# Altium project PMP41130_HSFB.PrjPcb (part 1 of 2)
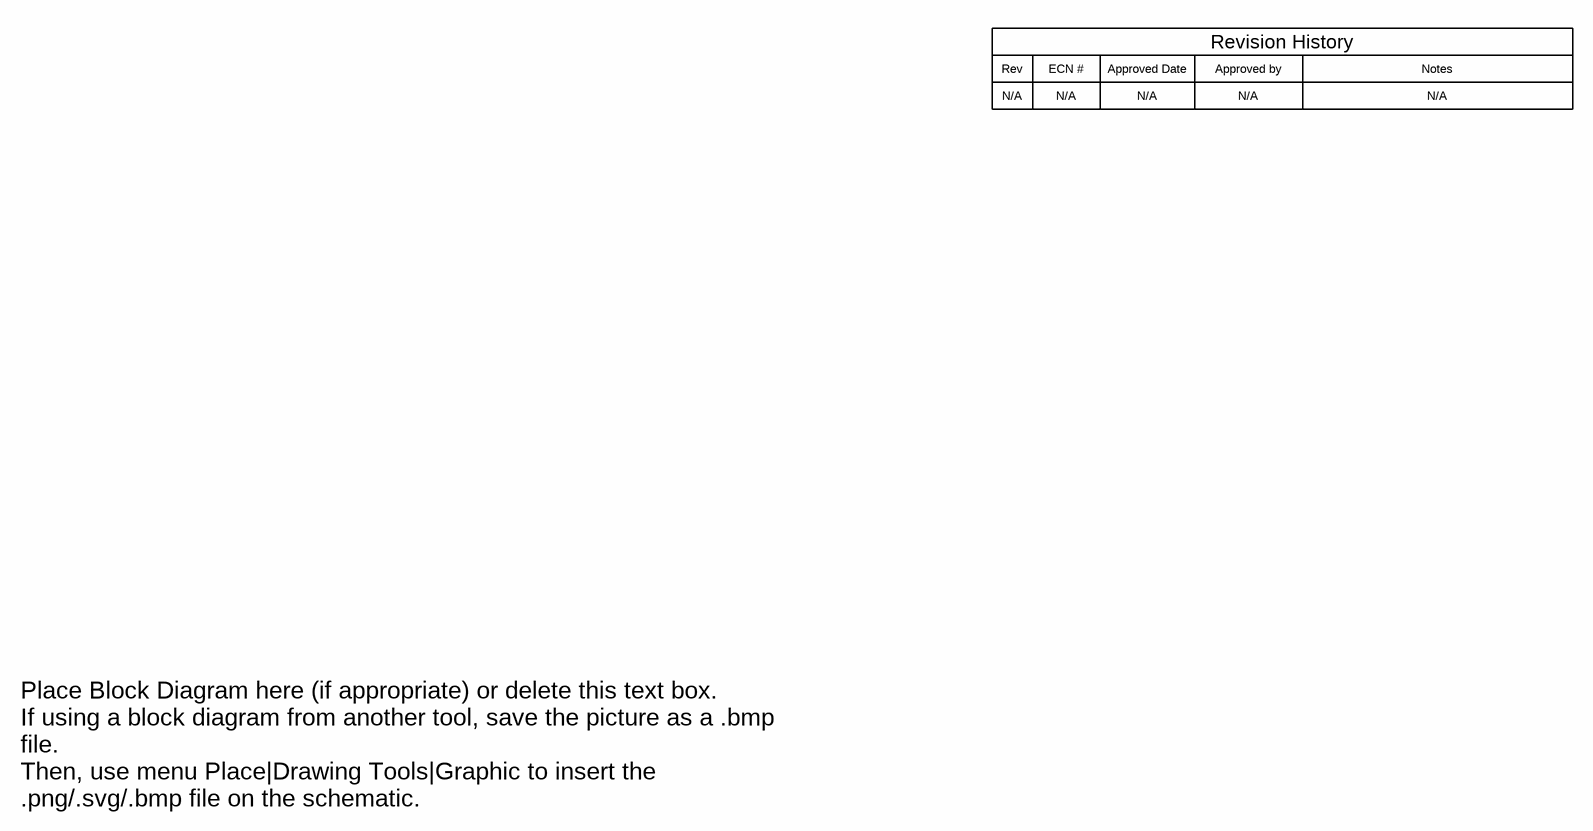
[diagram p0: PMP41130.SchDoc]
CopyrightYear: 2024; PCB_Layout: Xingqi (Eric) Chen; PCB_Rev: E1; PRJ_Customer: Public Release; PRJ_Engineer: Xingqi (Eric) Chen; PRJ_Number: PMP41130; PRJ_Title: PMP41130; SCH_Rev: E1; TechSupport: http://www.ti.com/support; TID: N/A
5 sheets, 369 parts. Net scope: global (net labels, ports and power ports of the same name join across sheets).
Board file: PMP41130_PCB.PcbDoc
Sheets:
  PMP41130.SchDoc
  PMP41130_PWR.SchDoc
  PMP41130_CTRL.SchDoc
  PMP41130_AUX.SchDoc
  PMP41130_Hardware.SchDoc

## Sheet PMP41130.SchDoc
size 431 x 279 mm; Date: Not shown in title block; ApprovedBy: Not shown in title block; CheckedBy: Not shown in title block; Author: Not shown in title block; CompanyName: Not shown in title block; Engineer: Not shown in title block; Organization: Not shown in title block; Address1: Not shown in title block; Address2: Not shown in title block; Address3: Not shown in title block; Address4: Not shown in title block; DocumentNumber: 1; Revision: Use project parameter SCH_Rev; SheetNumber: 1; SheetTotal: 5; PageSetup: Record=PageOptions¦CenterHorizontal=True¦CenterVertical=True¦PrintScale=1.00¦XCorrection=1.00¦YCorrection=1.00¦PrintKind=0¦BorderSize=5000000¦LeftOffset=0¦BottomOffset=0¦Orientation=2¦PaperLength=1000¦PaperWidth=1000¦Scale=100¦PaperSource=15¦PrintQuality=600¦MediaType=1¦DitherType=10¦PaperKind=Letter¦PrintScaleMode=1

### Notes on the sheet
- Rev
- N/A
- ECN #
- Approved Date
- Approved by
- Revision History
- Notes
- Place Block Diagram here (if appropriate) or delete this text box.
  If using a block diagram from another tool, save the picture as a .bmp file.
  Then, use menu Place|Drawing Tools|Graphic to insert the .png/.svg/.bmp file on the schematic.

## Sheet PMP41130_PWR.SchDoc
size A2; Date: Not shown in title block; ApprovedBy: Not shown in title block; CheckedBy: Not shown in title block; Author: Not shown in title block; CompanyName: Not shown in title block; Engineer: Not shown in title block; Organization: Not shown in title block; Address1: Not shown in title block; Address2: Not shown in title block; Address3: Not shown in title block; Address4: Not shown in title block; DocumentNumber: 1; Revision: Use project parameter SCH_Rev; SheetNumber: 2; SheetTotal: 5; PageSetup: Record=PageOptions¦CenterHorizontal=True¦CenterVertical=True¦PrintScale=0.69¦XCorrection=1.00¦YCorrection=1.00¦PrintKind=0¦BorderSize=5000000¦LeftOffset=0¦BottomOffset=0¦Orientation=2¦PaperLength=1000¦PaperWidth=1000¦Scale=100¦PaperSource=15¦PrintQuality=600¦MediaType=1¦DitherType=10¦PaperKind=Letter¦PrintScaleMode=1
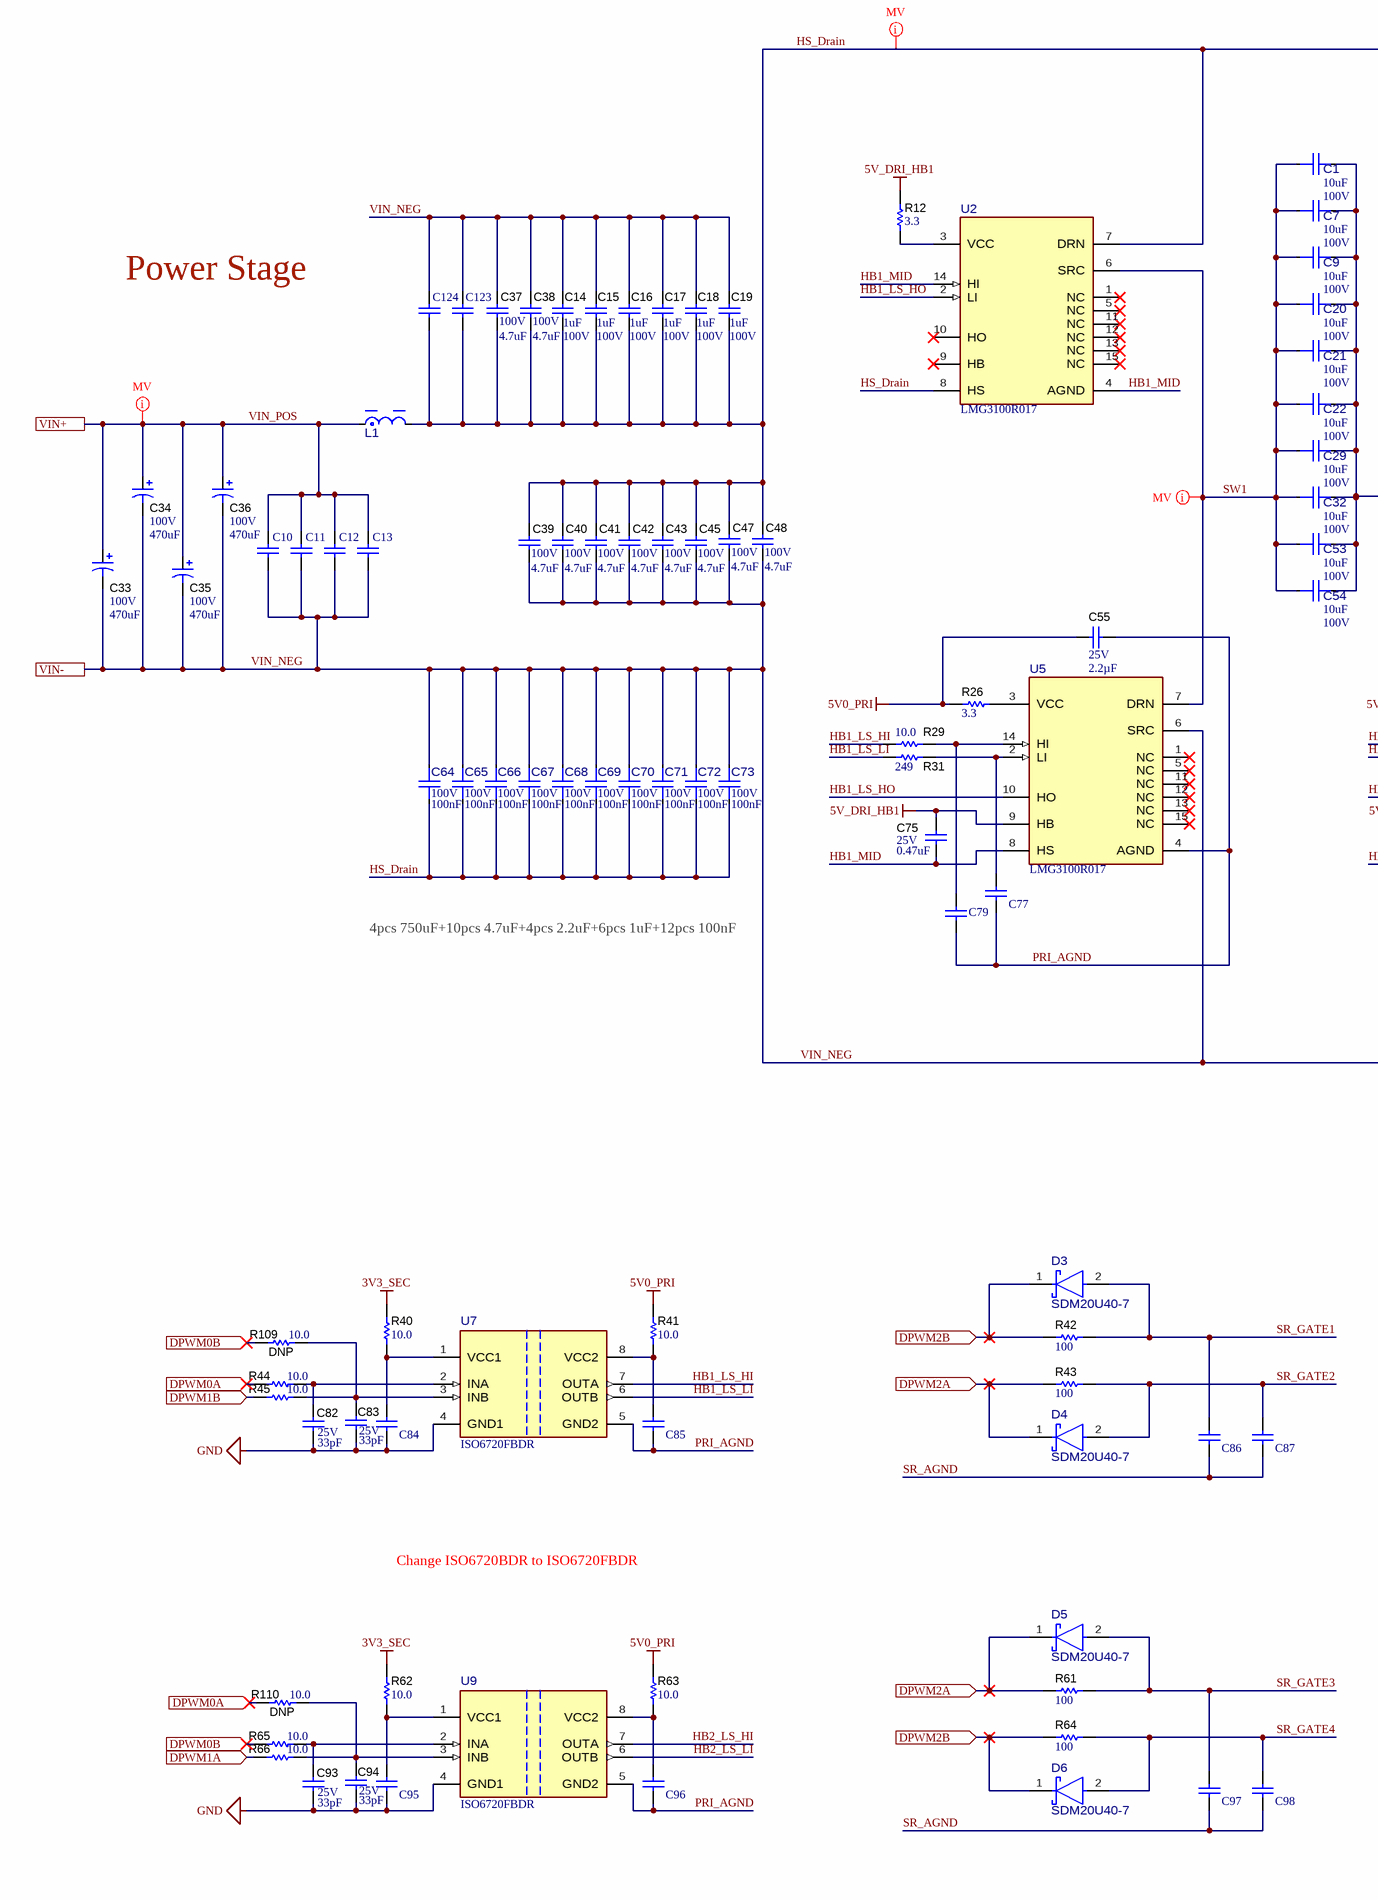
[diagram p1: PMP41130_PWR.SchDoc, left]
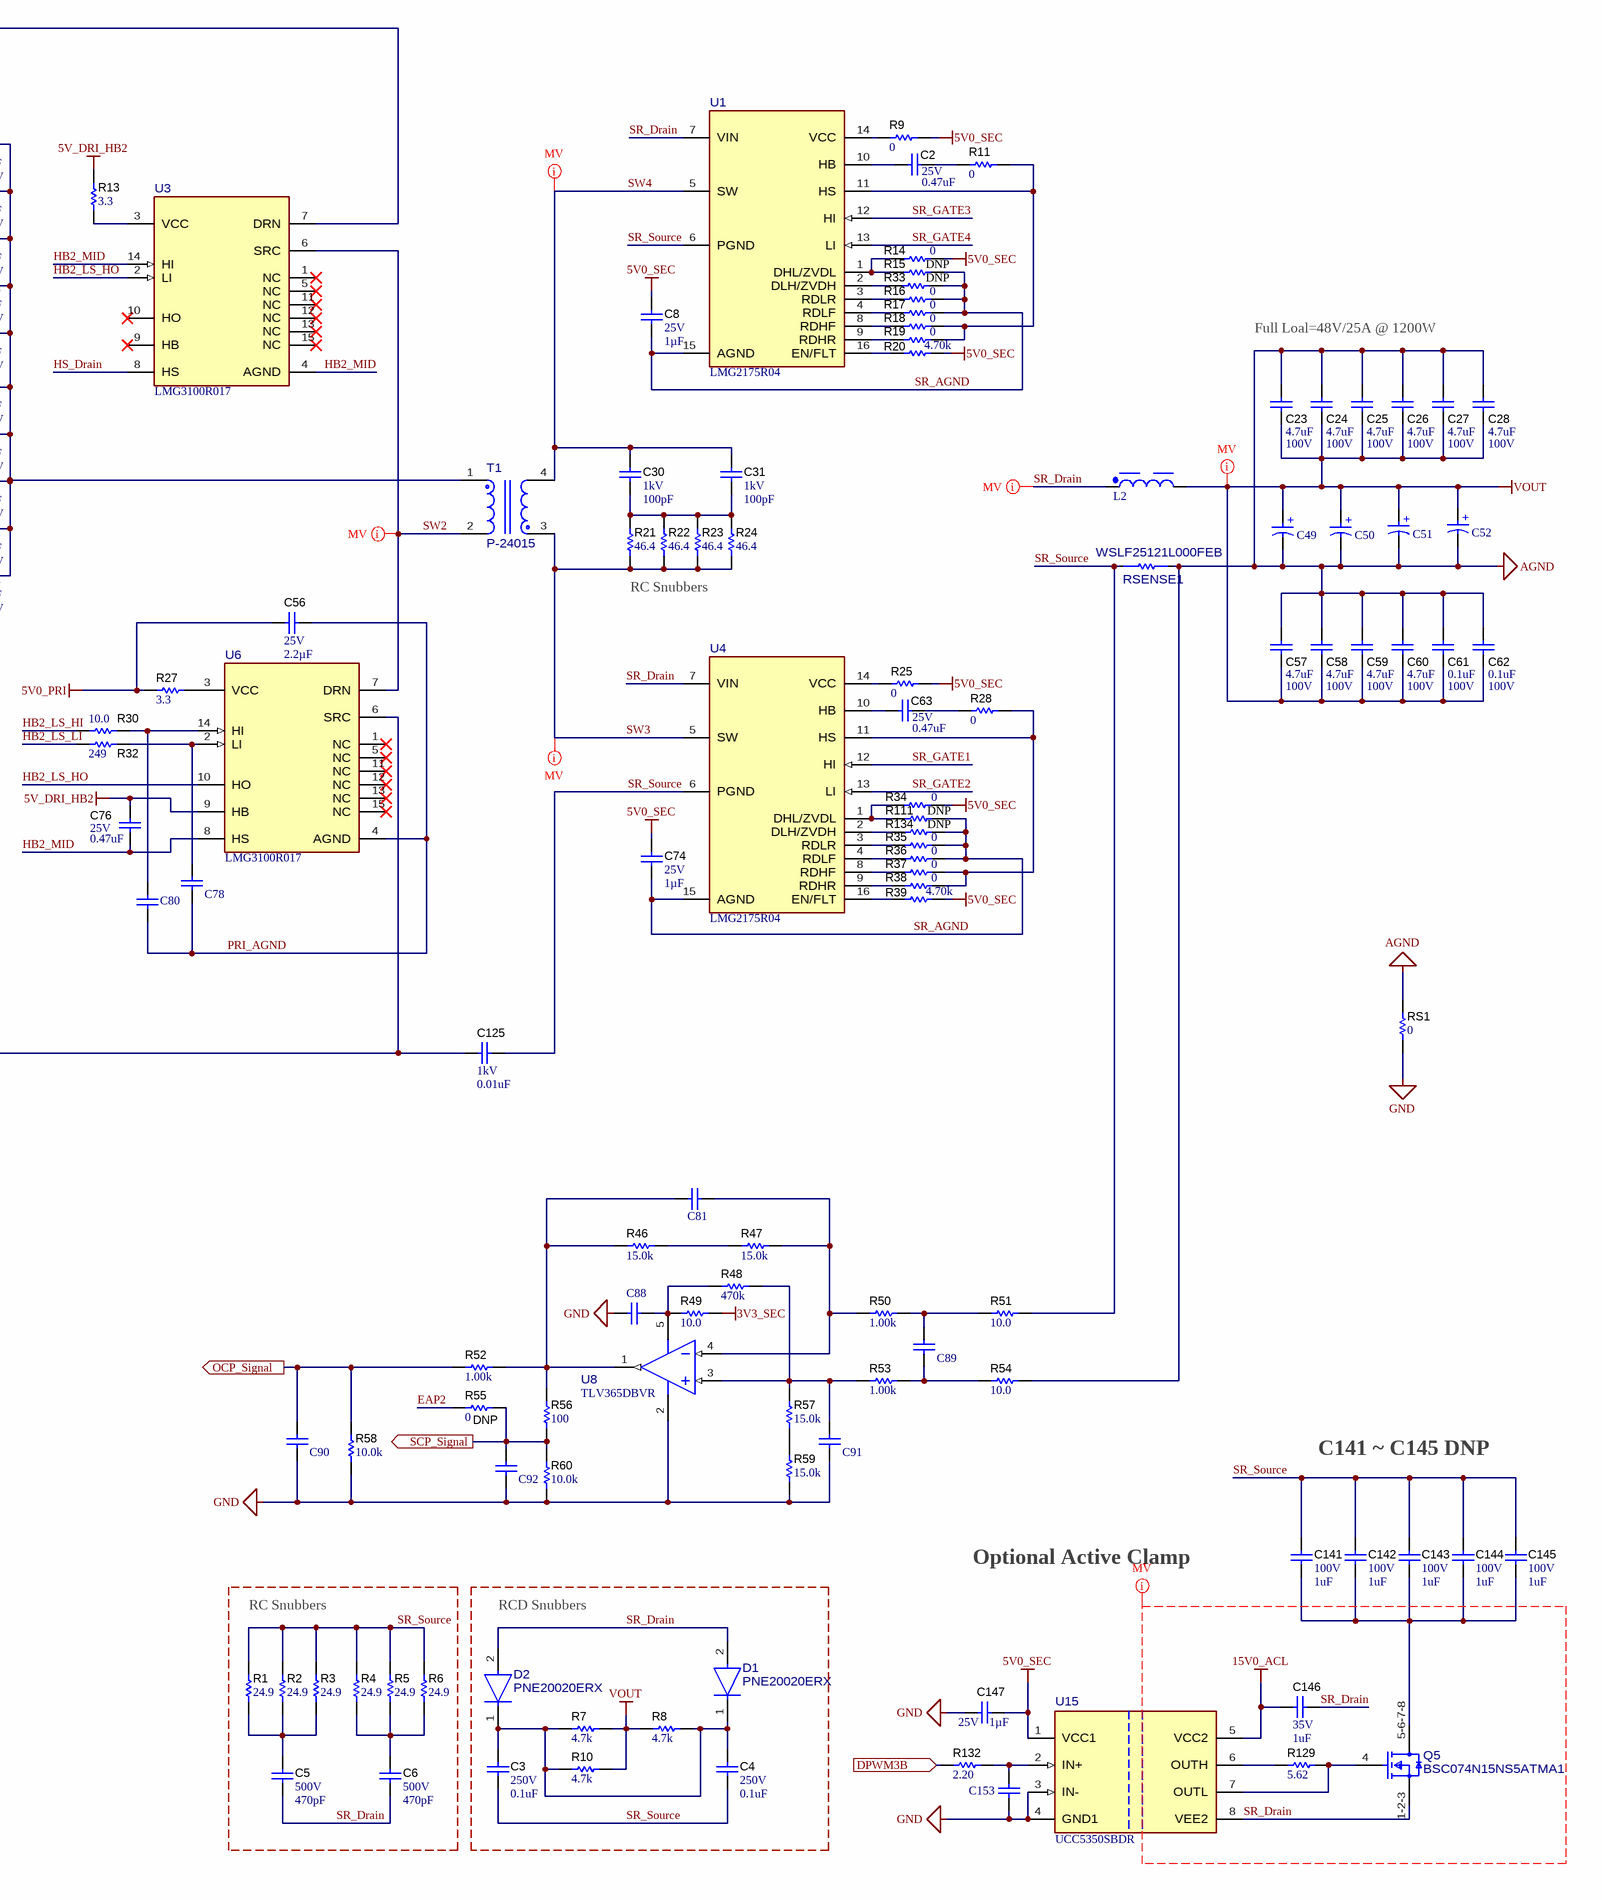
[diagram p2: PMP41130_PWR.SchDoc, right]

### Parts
C1  ValueDisplayed: 10uF  VDC_V: 100V  [FP-C3216X6S2A106K160AC_1206-MFG]  (hidden comment: C3216X6S2A106K160AC)
C2  VDC_V: 25V  ValueDisplayed: 0.47uF  [0402]  (hidden comment: GRM155R61E474KE01D)
C3  VDC_V: 250V  ValueDisplayed: 0.1uF  [0805_HV]  (hidden comment: C2012X7T2E104M125AE)
C4  VDC_V: 250V  ValueDisplayed: 0.1uF  [0805_HV]  (hidden comment: C2012X7T2E104M125AE)
C5  VDC_V: 500V  ValueDisplayed: 470pF  [1206]  (hidden comment: VJ1206Y471KXEAT5Z)
C6  VDC_V: 500V  ValueDisplayed: 470pF  [1206]  (hidden comment: VJ1206Y471KXEAT5Z)
C7  ValueDisplayed: 10uF  VDC_V: 100V  [FP-C3216X6S2A106K160AC_1206-MFG]  (hidden comment: C3216X6S2A106K160AC)
C8  VDC_V: 25V  ValueDisplayed: 1µF  [0402]  (hidden comment: GRM155R61E105MA12D)
C9  ValueDisplayed: 10uF  VDC_V: 100V  [FP-C3216X6S2A106K160AC_1206-MFG]  (hidden comment: C3216X6S2A106K160AC)
C10  885012209071  [WCAP-CSGP_1210_L3.2W2.5H2.5]  (value not drawn)
C11  885012209071  [WCAP-CSGP_1210_L3.2W2.5H2.5]  (value not drawn)
C12  885012209071  [WCAP-CSGP_1210_L3.2W2.5H2.5]  (value not drawn)
C13  885012209071  [WCAP-CSGP_1210_L3.2W2.5H2.5]  (value not drawn)
C14  VDC_V: 100V  ValueDisplayed: 1uF  [0805_HV]  (hidden comment: C2012X7S2A105K125AB)
C15  VDC_V: 100V  ValueDisplayed: 1uF  [0805_HV]  (hidden comment: C2012X7S2A105K125AB)
C16  VDC_V: 100V  ValueDisplayed: 1uF  [0805_HV]  (hidden comment: C2012X7S2A105K125AB)
C17  VDC_V: 100V  ValueDisplayed: 1uF  [0805_HV]  (hidden comment: C2012X7S2A105K125AB)
C18  VDC_V: 100V  ValueDisplayed: 1uF  [0805_HV]  (hidden comment: C2012X7S2A105K125AB)
C19  VDC_V: 100V  ValueDisplayed: 1uF  [0805_HV]  (hidden comment: C2012X7S2A105K125AB)
C20  ValueDisplayed: 10uF  VDC_V: 100V  [FP-C3216X6S2A106K160AC_1206-MFG]  (hidden comment: C3216X6S2A106K160AC)
C21  ValueDisplayed: 10uF  VDC_V: 100V  [FP-C3216X6S2A106K160AC_1206-MFG]  (hidden comment: C3216X6S2A106K160AC)
C22  ValueDisplayed: 10uF  VDC_V: 100V  [FP-C3216X6S2A106K160AC_1206-MFG]  (hidden comment: C3216X6S2A106K160AC)
C23  VDC_V: 100V  ValueDisplayed: 4.7uF  [1210]  (hidden comment: C3225X7S2A475K200AE)
C24  VDC_V: 100V  ValueDisplayed: 4.7uF  [1210]  (hidden comment: C3225X7S2A475K200AE)
C25  VDC_V: 100V  ValueDisplayed: 4.7uF  [1210]  (hidden comment: C3225X7S2A475K200AE)
C26  VDC_V: 100V  ValueDisplayed: 4.7uF  [1210]  (hidden comment: C3225X7S2A475K200AE)
C27  VDC_V: 100V  ValueDisplayed: 4.7uF  [1210]  (hidden comment: C3225X7S2A475K200AE)
C28  VDC_V: 100V  ValueDisplayed: 4.7uF  [1210]  (hidden comment: C3225X7S2A475K200AE)
C29  ValueDisplayed: 10uF  VDC_V: 100V  [FP-C3216X6S2A106K160AC_1206-MFG]  (hidden comment: C3216X6S2A106K160AC)
C30  VDC_V: 1kV  ValueDisplayed: 100pF  [1206]  (hidden comment: VJ1206A101JXGAT5Z)
C31  VDC_V: 1kV  ValueDisplayed: 100pF  [1206]  (hidden comment: VJ1206A101JXGAT5Z)
C32  ValueDisplayed: 10uF  VDC_V: 100V  [FP-C3216X6S2A106K160AC_1206-MFG]  (hidden comment: C3216X6S2A106K160AC)
C33  VDC_V: 100V  ValueDisplayed: 470uF  [M_1600x2500]  (hidden comment: ECA-2AM471)
C34  VDC_V: 100V  ValueDisplayed: 470uF  [M_1600x2500]  (hidden comment: ECA-2AM471)
C35  VDC_V: 100V  ValueDisplayed: 470uF  [M_1600x2500]  (hidden comment: ECA-2AM471)
C36  VDC_V: 100V  ValueDisplayed: 470uF  [M_1600x2500]  (hidden comment: ECA-2AM471)
C37  VDC_V: 100V  ValueDisplayed: 4.7uF  [1210]  (hidden comment: C3225X7S2A475K200AE)
C38  VDC_V: 100V  ValueDisplayed: 4.7uF  [1210]  (hidden comment: C3225X7S2A475K200AE)
C39  VDC_V: 100V  ValueDisplayed: 4.7uF  [1210]  (hidden comment: C3225X7S2A475K200AE)
C40  VDC_V: 100V  ValueDisplayed: 4.7uF  [1210]  (hidden comment: C3225X7S2A475K200AE)
C41  VDC_V: 100V  ValueDisplayed: 4.7uF  [1210]  (hidden comment: C3225X7S2A475K200AE)
C42  VDC_V: 100V  ValueDisplayed: 4.7uF  [1210]  (hidden comment: C3225X7S2A475K200AE)
C43  VDC_V: 100V  ValueDisplayed: 4.7uF  [1210]  (hidden comment: C3225X7S2A475K200AE)
C45  VDC_V: 100V  ValueDisplayed: 4.7uF  [1210]  (hidden comment: C3225X7S2A475K200AE)
C47  VDC_V: 100V  ValueDisplayed: 4.7uF  [1210]  (hidden comment: C3225X7S2A475K200AE)
C48  VDC_V: 100V  ValueDisplayed: 4.7uF  [1210]  (hidden comment: C3225X7S2A475K200AE)
C49  865080863009  [WCAP-ASLI_D16H17]  (value not drawn)
C50  865080863009  [WCAP-ASLI_D16H17]  (value not drawn)
C51  865080863009  [WCAP-ASLI_D16H17]  (value not drawn)
C52  865080863009  [WCAP-ASLI_D16H17]  (value not drawn)
C53  ValueDisplayed: 10uF  VDC_V: 100V  [FP-C3216X6S2A106K160AC_1206-MFG]  (hidden comment: C3216X6S2A106K160AC)
C54  ValueDisplayed: 10uF  VDC_V: 100V  [FP-C3216X6S2A106K160AC_1206-MFG]  (hidden comment: C3216X6S2A106K160AC)
C55  VDC_V: 25V  ValueDisplayed: 2.2µF  [0402]  (hidden comment: GRM155R61E225ME15D)
C56  VDC_V: 25V  ValueDisplayed: 2.2µF  [0402]  (hidden comment: GRM155R61E225ME15D)
C57  VDC_V: 100V  ValueDisplayed: 4.7uF  [1210]  (hidden comment: C3225X7S2A475K200AE)
C58  VDC_V: 100V  ValueDisplayed: 4.7uF  [1210]  (hidden comment: C3225X7S2A475K200AE)
C59  VDC_V: 100V  ValueDisplayed: 4.7uF  [1210]  (hidden comment: C3225X7S2A475K200AE)
C60  VDC_V: 100V  ValueDisplayed: 4.7uF  [1210]  (hidden comment: C3225X7S2A475K200AE)
C61  VDC_V: 100V  ValueDisplayed: 0.1uF  [1210]  (hidden comment: VJ1210Y104KBBAT4X)
C62  VDC_V: 100V  ValueDisplayed: 0.1uF  [1210]  (hidden comment: VJ1210Y104KBBAT4X)
C63  VDC_V: 25V  ValueDisplayed: 0.47uF  [0402]  (hidden comment: GRM155R61E474KE01D)
C64  VDC_V: 100V  Cap_F: 100nF  [FP-885012206120_0603-MFG]  (hidden comment: 885012206120)
C65  VDC_V: 100V  Cap_F: 100nF  [FP-885012206120_0603-MFG]  (hidden comment: 885012206120)
C66  VDC_V: 100V  Cap_F: 100nF  [FP-885012206120_0603-MFG]  (hidden comment: 885012206120)
C67  VDC_V: 100V  Cap_F: 100nF  [FP-885012206120_0603-MFG]  (hidden comment: 885012206120)
C68  VDC_V: 100V  Cap_F: 100nF  [FP-885012206120_0603-MFG]  (hidden comment: 885012206120)
C69  VDC_V: 100V  Cap_F: 100nF  [FP-885012206120_0603-MFG]  (hidden comment: 885012206120)
C70  VDC_V: 100V  Cap_F: 100nF  [FP-885012206120_0603-MFG]  (hidden comment: 885012206120)
C71  VDC_V: 100V  Cap_F: 100nF  [FP-885012206120_0603-MFG]  (hidden comment: 885012206120)
C72  VDC_V: 100V  Cap_F: 100nF  [FP-885012206120_0603-MFG]  (hidden comment: 885012206120)
C73  VDC_V: 100V  Cap_F: 100nF  [FP-885012206120_0603-MFG]  (hidden comment: 885012206120)
C74  VDC_V: 25V  ValueDisplayed: 1µF  [0402]  (hidden comment: GRM155R61E105MA12D)
C75  VDC_V: 25V  ValueDisplayed: 0.47uF  [0402]  (hidden comment: GRM155R61E474KE01D)
C76  VDC_V: 25V  ValueDisplayed: 0.47uF  [0402]  (hidden comment: GRM155R61E474KE01D)
C77  885012205055  [WCAP-CSGP_0402_L1W0.5H0.5]  (value not drawn)
C78  885012205055  [WCAP-CSGP_0402_L1W0.5H0.5]  (value not drawn)
C79  885012005058  [WCAP-CSGP_0402_L1W0.5H0.5]  (value not drawn)
C80  885012005058  [WCAP-CSGP_0402_L1W0.5H0.5]  (value not drawn)
C81  885012005058  [WCAP-CSGP_0402_L1W0.5H0.5]  (value not drawn)
C82  VDC_V: 25V  ValueDisplayed: 33pF  [0402]  (hidden comment: 885012005043)
C83  VDC_V: 25V  ValueDisplayed: 33pF  [0402]  (hidden comment: 885012005043)
C84  885012205037  [WCAP-CSGP_0402_L1W0.5H0.5]  (value not drawn)
C85  885012205037  [WCAP-CSGP_0402_L1W0.5H0.5]  (value not drawn)
C86  885012005058  [WCAP-CSGP_0402_L1W0.5H0.5]  (value not drawn)
C87  885012005058  [WCAP-CSGP_0402_L1W0.5H0.5]  (value not drawn)
C88  885012205018  [WCAP-CSGP_0402_L1W0.5H0.5]  (value not drawn)
C89  885012005067  [WCAP-CSGP_0402_L1W0.5H0.5]  (value not drawn)
C90  885012205050  [WCAP-CSGP_0402_L1W0.5H0.5]  (value not drawn)
C91  885012005058  [WCAP-CSGP_0402_L1W0.5H0.5]  (value not drawn)
C92  885392005114  [WCAP-CSRF_0402_L1W0.5H0.5]  (value not drawn)
C93  VDC_V: 25V  ValueDisplayed: 33pF  [0402]  (hidden comment: 885012005043)
C94  VDC_V: 25V  ValueDisplayed: 33pF  [0402]  (hidden comment: 885012005043)
C95  885012205037  [WCAP-CSGP_0402_L1W0.5H0.5]  (value not drawn)
C96  885012205037  [WCAP-CSGP_0402_L1W0.5H0.5]  (value not drawn)
C97  885012005058  [WCAP-CSGP_0402_L1W0.5H0.5]  (value not drawn)
C98  885012005058  [WCAP-CSGP_0402_L1W0.5H0.5]  (value not drawn)
C123  885012208118  [WCAP-CSGP_1206_L3.2W1.6H1.25]  (value not drawn)
C124  885012208118  [WCAP-CSGP_1206_L3.2W1.6H1.25]  (value not drawn)
C125  VDC_V: 1kV  ValueDisplayed: 0.01uF  [1206]  (hidden comment: VJ1206Y103KXGAT5Z)
C141  VDC_V: 100V  ValueDisplayed: 1uF  [0805_HV]  (hidden comment: C2012X7S2A105K125AB)  (no BOM)
C142  VDC_V: 100V  ValueDisplayed: 1uF  [0805_HV]  (hidden comment: C2012X7S2A105K125AB)  (no BOM)
C143  VDC_V: 100V  ValueDisplayed: 1uF  [0805_HV]  (hidden comment: C2012X7S2A105K125AB)  (no BOM)
C144  VDC_V: 100V  ValueDisplayed: 1uF  [0805_HV]  (hidden comment: C2012X7S2A105K125AB)  (no BOM)
C145  VDC_V: 100V  ValueDisplayed: 1uF  [0805_HV]  (hidden comment: C2012X7S2A105K125AB)  (no BOM)
C146  VDC_V: 35V  ValueDisplayed: 1uF  [0402M]  (hidden comment: C1005JB1V105K050BC)
C147  VDC_V: 25V  ValueDisplayed: 1µF  [0402]  (hidden comment: GRM155R61E105MA12D)
C153  885012005059  [WCAP-CSGP_0402_L1W0.5H0.5]  (value not drawn)
D1  PNE20020ERX  [FP-PNE20020ERX_SOD123W-MFG]
D2  PNE20020ERX  [FP-PNE20020ERX_SOD123W-MFG]
D3  SDM20U40-7  [FP-SDM20U40-7_SOD523-MFG]
D4  SDM20U40-7  [FP-SDM20U40-7_SOD523-MFG]
D5  SDM20U40-7  [FP-SDM20U40-7_SOD523-MFG]
D6  SDM20U40-7  [FP-SDM20U40-7_SOD523-MFG]
L1  74439369010  [FP-74439369010_SMD_11MM6_10MM5-MFG]  (value not drawn)
L2  74439370068  [WE-XHMI_1510_L16.4W15.4H10]  (value not drawn)
Q5  BSC074N15NS5ATMA1  [FP-BSC074N15NS5ATMA1_PG-TSON-8-3-MFG]
R1  ValueDisplayed: 24.9  [1206]  (hidden comment: RC1206FR-0724R9L)
R2  ValueDisplayed: 24.9  [1206]  (hidden comment: RC1206FR-0724R9L)
R3  ValueDisplayed: 24.9  [1206]  (hidden comment: RC1206FR-0724R9L)
R4  ValueDisplayed: 24.9  [1206]  (hidden comment: RC1206FR-0724R9L)
R5  ValueDisplayed: 24.9  [1206]  (hidden comment: RC1206FR-0724R9L)
R6  ValueDisplayed: 24.9  [1206]  (hidden comment: RC1206FR-0724R9L)
R7  ValueDisplayed: 4.7k  [2512]  (hidden comment: CRCW25124K70JNEG)
R8  ValueDisplayed: 4.7k  [2512]  (hidden comment: CRCW25124K70JNEG)
R9  ValueDisplayed: 0  [0402]  (hidden comment: RC0402JR-070RL)
R10  ValueDisplayed: 4.7k  [2512]  (hidden comment: CRCW25124K70JNEG)
R11  ValueDisplayed: 0  [0402]  (hidden comment: RC0402JR-070RL)
R12  ValueDisplayed: 3.3  [0402]  (hidden comment: CRCW04023R30JNED)
R13  ValueDisplayed: 3.3  [0402]  (hidden comment: CRCW04023R30JNED)
R14  ValueDisplayed: 0  [0402]  (hidden comment: RC0402JR-070RL)
R15  ValueDisplayed: DNP  [0402]  (hidden comment: ERJ-2RKF1002X)  (no BOM)
R16  ValueDisplayed: 0  [0402]  (hidden comment: RC0402JR-070RL)
R17  ValueDisplayed: 0  [0402]  (hidden comment: RC0402JR-070RL)
R18  ValueDisplayed: 0  [0402]  (hidden comment: RC0402JR-070RL)
R19  ValueDisplayed: 0  [0402]  (hidden comment: RC0402JR-070RL)
R20  ValueDisplayed: 4.70k  [0402]  (hidden comment: ERJ-2RKF4701X)
R21  ValueDisplayed: 46.4  [1206]  (hidden comment: RC1206FR-0746R4L)
R22  ValueDisplayed: 46.4  [1206]  (hidden comment: RC1206FR-0746R4L)
R23  ValueDisplayed: 46.4  [1206]  (hidden comment: RC1206FR-0746R4L)
R24  ValueDisplayed: 46.4  [1206]  (hidden comment: RC1206FR-0746R4L)
R25  ValueDisplayed: 0  [0402]  (hidden comment: RC0402JR-070RL)
R26  ValueDisplayed: 3.3  [0402]  (hidden comment: CRCW04023R30JNED)
R27  ValueDisplayed: 3.3  [0402]  (hidden comment: CRCW04023R30JNED)
R28  ValueDisplayed: 0  [0402]  (hidden comment: RC0402JR-070RL)
R29  ValueDisplayed: 10.0  [0402]  (hidden comment: RK73H1ETTP10R0F)
R30  ValueDisplayed: 10.0  [0402]  (hidden comment: RK73H1ETTP10R0F)
R31  ValueDisplayed: 249  [0402]  (hidden comment: CRCW0402249RFKED)
R32  ValueDisplayed: 249  [0402]  (hidden comment: CRCW0402249RFKED)
R33  ValueDisplayed: DNP  [0402]  (hidden comment: ERJ-2RKF1002X)  (no BOM)
R34  ValueDisplayed: 0  [0402]  (hidden comment: RC0402JR-070RL)
R35  ValueDisplayed: 0  [0402]  (hidden comment: RC0402JR-070RL)
R36  ValueDisplayed: 0  [0402]  (hidden comment: RC0402JR-070RL)
R37  ValueDisplayed: 0  [0402]  (hidden comment: RC0402JR-070RL)
R38  ValueDisplayed: 0  [0402]  (hidden comment: RC0402JR-070RL)
R39  ValueDisplayed: 4.70k  [0402]  (hidden comment: ERJ-2RKF4701X)
R40  ValueDisplayed: 10.0  [0402]  (hidden comment: RK73H1ETTP10R0F)
R41  ValueDisplayed: 10.0  [0402]  (hidden comment: RK73H1ETTP10R0F)
R42  ValueDisplayed: 100  [0402]  (hidden comment: RMCF0402JT100R)
R43  ValueDisplayed: 100  [0402]  (hidden comment: RMCF0402JT100R)
R44  ValueDisplayed: 10.0  [0402]  (hidden comment: RK73H1ETTP10R0F)
R45  ValueDisplayed: 10.0  [0402]  (hidden comment: RK73H1ETTP10R0F)
R46  ValueDisplayed: 15.0k  [0402]  (hidden comment: RC0402FR-0715KL)
R47  ValueDisplayed: 15.0k  [0402]  (hidden comment: RC0402FR-0715KL)
R48  ValueDisplayed: 470k  [0402]  (hidden comment: RC0402FR-07470KL)
R49  ValueDisplayed: 10.0  [0402]  (hidden comment: MCR01MZPF10R0)
R50  ValueDisplayed: 1.00k  [0402]  (hidden comment: ERJ-2RKF1001X)
R51  ValueDisplayed: 10.0  [0402]  (hidden comment: MCR01MZPF10R0)
R52  ValueDisplayed: 1.00k  [0402]  (hidden comment: ERJ-2RKF1001X)
R53  ValueDisplayed: 1.00k  [0402]  (hidden comment: ERJ-2RKF1001X)
R54  ValueDisplayed: 10.0  [0402]  (hidden comment: MCR01MZPF10R0)
R55  DNP  ValueDisplayed: 0  [0402]  (no BOM)
R56  ValueDisplayed: 100  [0402]  (hidden comment: RMCF0402JT100R)
R57  ValueDisplayed: 15.0k  [0402]  (hidden comment: RC0402FR-0715KL)
R58  ValueDisplayed: 10.0k  [0402]  (hidden comment: ERJ-2RKF1002X)
R59  ValueDisplayed: 15.0k  [0402]  (hidden comment: RC0402FR-0715KL)
R60  ValueDisplayed: 10.0k  [0402]  (hidden comment: ERJ-2RKF1002X)
R61  ValueDisplayed: 100  [0402]  (hidden comment: RMCF0402JT100R)
R62  ValueDisplayed: 10.0  [0402]  (hidden comment: RK73H1ETTP10R0F)
R63  ValueDisplayed: 10.0  [0402]  (hidden comment: RK73H1ETTP10R0F)
R64  ValueDisplayed: 100  [0402]  (hidden comment: RMCF0402JT100R)
R65  ValueDisplayed: 10.0  [0402]  (hidden comment: RK73H1ETTP10R0F)
R66  ValueDisplayed: 10.0  [0402]  (hidden comment: RK73H1ETTP10R0F)
R109  DNP  ValueDisplayed: 10.0  [0402]  (no BOM)
R110  DNP  ValueDisplayed: 10.0  [0402]  (no BOM)
R111  ValueDisplayed: DNP  [0402]  (hidden comment: ERJ-2RKF1002X)  (no BOM)
R129  ValueDisplayed: 5.62  [0402]  (hidden comment: CRCW04025R62FKED)
R132  ValueDisplayed: 2.20  [0402]  (hidden comment: RCS04022R20FKED)
R134  ValueDisplayed: DNP  [0402]  (hidden comment: ERJ-2RKF1002X)  (no BOM)
RS1  ValueDisplayed: 0  [1206]  (hidden comment: RC1206JR-070RL)
RSENSE1  WSLF25121L000FEB  [FP-WSLF25121L000FEB_2512-MFG]
T1  P-24015  [FP-P-24015_SMT_XFRMR_29MM0_31MM1-MFG]
U1  LMG2175R04  [VBN0016A-MFG]
U2  LMG3100R017  [VBE0015A-MFG]
U3  LMG3100R017  [VBE0015A-MFG]
U4  LMG2175R04  [VBN0016A-MFG]
U5  LMG3100R017  [VBE0015A-MFG]
U6  LMG3100R017  [VBE0015A-MFG]
U7  ISO6720FBDR  [D0008A-MFG]
U8  TLV365DBVR  [DBV0005A-MFG]
U9  ISO6720FBDR  [D0008A-MFG]
U15  UCC5350SBDR  [D0008A-MFG]

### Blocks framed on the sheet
RC Snubbers: C5 C6 R1-R6
RCD Snubbers: C3 C4 D1 D2 R7 R8 R10

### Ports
DPWM0A (in), DPWM0B (in), DPWM1A (in), DPWM1B (in), DPWM2A (in), DPWM2B (in), DPWM3B (in), OCP_Signal (out), SCP_Signal (out), VIN+, VIN-

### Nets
3V3_SEC: R40.2 R49.2 R62.2
5V0_PRI: C55.2 C56.2 R26.1 R27.1 R41.2 R63.2
5V0_SEC: C8.2 C74.2 C147.2 R9.2 R14.2 R20.2 R25.2 R34.2 R39.2 U15.1(VCC1)
5V_DRI_HB1: C75.1 R12.2 U5.9(HB)
5V_DRI_HB2: C76.1 R13.2 U6.9(HB)
15V0_ACL: C146.2 U15.5(VCC2)
AGND: C23.1 C24.1 C25.1 C26.1 C27.1 C28.1 C49.2(N) C50.2(N) C51.2(N) C52.2(N) C57.1 C58.1 C59.1 C60.1 C61.1 C62.1 R54.2 RS1.1 RSENSE1.2
GND: C82.2 C83.2 C84.2 C88.1 C90.2 C91.2 C92.2 C93.2 C94.2 C95.2 C147.1 C153.1 R58.1 R59.1 R60.1 RS1.2 U7.4(GND1) U8.2(V-) U9.4(GND1) U15.3(IN-) U15.4(GND1)
VOUT: C23.2 C24.2 C25.2 C26.2 C27.2 C28.2 C49.1(P) C50.1(P) C51.1(P) C52.1(P) C57.2 C58.2 C59.2 C60.2 C61.2 C62.2 L2.2 R7.2 R8.1 R10.2
DPWM0A: R44.2 R110.2 ; port DPWM0A
DPWM0B: R65.2 R109.2 ; port DPWM0B
DPWM1A: R66.2 ; port DPWM1A
DPWM1B: R45.2 ; port DPWM1B
DPWM2A: D4.1(CATHODE) D5.1(CATHODE) R43.1 R61.1 ; port DPWM2A
DPWM2B: D3.1(CATHODE) D6.1(CATHODE) R42.1 R64.1 ; port DPWM2B
DPWM3B: R132.1 ; port DPWM3B
EAP2: R55.1
HB1_LS_HI: R29.2 U7.7(OUTA)
HB1_LS_HO: U2.2(LI) U5.10(HO)
HB1_LS_LI: R31.2 U7.6(OUTB)
HB1_MID: C75.2 U2.4(AGND) U2.14(HI) U5.8(HS)
HB2_LS_HI: R30.2 U9.7(OUTA)
HB2_LS_HO: U3.2(LI) U6.10(HO)
HB2_LS_LI: R32.2 U9.6(OUTB)
HB2_MID: C76.2 U3.4(AGND) U3.14(HI) U6.8(HS)
HS_Drain: C14.2 C15.2 C16.2 C17.2 C18.2 C19.2 C37.2 C38.2 C39.1 C40.1 C41.1 C42.1 C43.1 C45.1 C47.1 C48.1 C64.2 C65.2 C66.2 C67.2 C68.2 C69.2 C70.2 C71.2 C72.2 C73.2 C123.2 C124.2 L1.2 U2.7(DRN) U2.8(HS) U3.7(DRN) U3.8(HS)
OCP_Signal: C90.1 R52.1 R58.2 ; port OCP_Signal
PRI_AGND: C55.1 C56.1 C77.2 C78.2 C79.2 C80.2 C85.2 C96.2 U5.4(AGND) U6.4(AGND) U7.5(GND2) U9.5(GND2)
SCP_Signal: C92.1 R55.2 R56.1 R60.2 ; port SCP_Signal
SR_AGND: C8.1 C74.1 C86.2 C87.2 C97.2 C98.2 R15.2 R16.2 R17.2 R33.2 R35.2 R36.2 R111.2 R134.2 U1.15(AGND) U4.15(AGND)
SR_Drain: C5.2 C6.2 C146.1 D1.2(A) D2.2(A) L2.1 Q5.1-2-3(S) U1.7(VIN) U4.7(VIN) U15.8(VEE2)
SR_GATE1: C86.1 D3.2(ANODE) R42.2 U4.12(HI)
SR_GATE2: C87.1 D4.2(ANODE) R43.2 U4.13(LI)
SR_GATE3: C97.1 D5.2(ANODE) R61.2 U1.12(HI)
SR_GATE4: C98.1 D6.2(ANODE) R64.2 U1.13(LI)
SR_Source: C3.2 C4.2 C125.1 C141.1 C142.1 C143.1 C144.1 C145.1 R1.2 R2.2 R3.2 R4.2 R5.2 R6.2 R51.2 RSENSE1.1 U1.6(PGND) U4.6(PGND)
SW1: C1.1 C7.1 C9.1 C20.1 C21.1 C22.1 C29.1 C32.1 C53.1 C54.1 U2.6(SRC) U5.7(DRN)
SW2: T1.2 U3.6(SRC) U6.7(DRN)
SW3: R21.2 R22.2 R23.2 R24.2 T1.3 U4.5(SW)
SW4: C30.2 C31.2 T1.4 U1.5(SW)
VIN_NEG: C10.2 C11.2 C12.2 C13.2 C14.1 C15.1 C16.1 C17.1 C18.1 C19.1 C33.2(-) C34.2(-) C35.2(-) C36.2(-) C37.1 C38.1 C39.2 C40.2 C41.2 C42.2 C43.2 C45.2 C47.2 C48.2 C64.1 C65.1 C66.1 C67.1 C68.1 C69.1 C70.1 C71.1 C72.1 C73.1 C123.1 C124.1 C125.2 U5.6(SRC) U6.6(SRC) ; port VIN-
VIN_POS: C10.1 C11.1 C12.1 C13.1 C33.1(+) C34.1(+) C35.1(+) C36.1(+) L1.1 ; port VIN+
NetC1_2: C1.2 C7.2 C9.2 C20.2 C21.2 C22.2 C29.2 C32.2 C53.2 C54.2 T1.1
NetC2_1: C2.1 R11.1
NetC2_2: C2.2 U1.10(HB)
NetC3_1: C3.1 C4.1 D1.1(K) D2.1(K) R7.1 R8.2 R10.1
NetC5_1: C5.1 R1.1 R2.1 R3.1
NetC6_1: C6.1 R4.1 R5.1 R6.1
NetC30_1: C30.1 C31.1 R21.1 R22.1 R23.1 R24.1
NetC63_1: C63.1 R28.1
NetC63_2: C63.2 U4.10(HB)
NetC77_1: C77.1 R31.1 U5.2(LI)
NetC78_1: C78.1 R32.1 U6.2(LI)
NetC79_1: C79.1 R29.1 U5.14(HI)
NetC80_1: C80.1 R30.1 U6.14(HI)
NetC81_1: C81.1 R46.1 R52.2 R56.2 U8.1(VOUT)
NetC81_2: C81.2 R47.2 R50.1 U8.4(-IN)
NetC82_1: C82.1 R44.1 U7.2(INA)
NetC83_1: C83.1 R45.1 R109.1 U7.3(INB)
NetC84_1: C84.1 R40.1 U7.1(VCC1)
NetC85_1: C85.1 R41.1 U7.8(VCC2)
NetC88_2: C88.2 R48.1 R49.1 U8.5(V+)
NetC89_1: C89.1 R53.2 R54.1
NetC89_2: C89.2 R50.2 R51.1
NetC91_1: C91.1 R48.2 R53.1 R57.2 U8.3(+IN)
NetC93_1: C93.1 R65.1 U9.2(INA)
NetC94_1: C94.1 R66.1 R110.1 U9.3(INB)
NetC95_1: C95.1 R62.1 U9.1(VCC1)
NetC96_1: C96.1 R63.1 U9.8(VCC2)
NetC141_2: C141.2 C142.2 C143.2 C144.2 C145.2 Q5.5-6-7-8(D)
NetC153_2: C153.2 R132.2 U15.2(IN+)
NetQ5_4: Q5.4(G) R129.2 U15.7(OUTL)
NetR9_1: R9.1 U1.14(VCC)
NetR11_2: R11.2 R18.2 R19.2 U1.11(HS)
NetR12_1: R12.1 U2.3(VCC)
NetR13_1: R13.1 U3.3(VCC)
NetR14_1: R14.1 R15.1 U1.1(DHL/ZVDL)
NetR16_1: R16.1 U1.3(RDLR)
NetR17_1: R17.1 U1.4(RDLF)
NetR18_1: R18.1 U1.8(RDHF)
NetR19_1: R19.1 U1.9(RDHR)
NetR20_1: R20.1 U1.16(EN/FLT)
NetR25_1: R25.1 U4.14(VCC)
NetR26_2: R26.2 U5.3(VCC)
NetR27_2: R27.2 U6.3(VCC)
NetR28_2: R28.2 R37.2 R38.2 U4.11(HS)
NetR33_1: R33.1 U1.2(DLH/ZVDH)
NetR34_1: R34.1 R111.1 U4.1(DHL/ZVDL)
NetR35_1: R35.1 U4.3(RDLR)
NetR36_1: R36.1 U4.4(RDLF)
NetR37_1: R37.1 U4.8(RDHF)
NetR38_1: R38.1 U4.9(RDHR)
NetR39_1: R39.1 U4.16(EN/FLT)
NetR46_2: R46.2 R47.1
NetR57_1: R57.1 R59.2
NetR129_1: R129.1 U15.6(OUTH)
NetR134_1: R134.1 U4.2(DLH/ZVDH)

Not connected (* = marked no-connect by the designer): U2 1(NC)* 5(NC)* 9(HB)* 10(HO)* 11(NC)* 12(NC)* 13(NC)* 15(NC)*; U3 1(NC)* 5(NC)* 9(HB)* 10(HO)* 11(NC)* 12(NC)* 13(NC)* 15(NC)*; U5 1(NC)* 5(NC)* 11(NC)* 12(NC)* 13(NC)* 15(NC)*; U6 1(NC)* 5(NC)* 11(NC)* 12(NC)* 13(NC)* 15(NC)*

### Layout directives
net class MIDVOLTAGE: 15V0_ACL, HS_Drain, SR_Drain, SW1, SW2, SW3, SW4, VIN_POS, VOUT

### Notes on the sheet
- Power Stage
- Full Loal=48V/25A @ 1200W
- RC Snubbers
- 4pcs 750uF+10pcs 4.7uF+4pcs 2.2uF+6pcs 1uF+12pcs 100nF
- C141 ~ C145 DNP
- Change ISO6720BDR to ISO6720FBDR
- Optional Active Clamp

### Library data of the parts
C1 C7 C9 C20-C22 C29 C32 C53 C54 = CMP-0098402-1: 10 µF ±10% 100V Ceramic Capacitor X6S 1206 (3216 Metric); Manufacturer: TDK; AEC Qualified: No; Cap_F: 10µF; SizeZ_mm: 1.9mm; TempCo: 22%; Value: 10µF
C2 C63 C75 C76 = CMP-0064928-2: CAP, CERM, 0.47 uF, 25 V,+/- 10%, X5R, 0402; Manufacturer: MuRata; TaMin_C: -55°C; Polarized: N; SizeAreaWB_mm2: 3; Value1: Unknown; U/M: EA; Value: 0.47uF; TaMax_C: 85°C; SizeZ_mm: 0.6; SizeX_mm: 1; SizeY_mm: 0.5; Cap_F: 470nF; AEC Category: Q200
C3 C4 = CMP-0064955-1: CAP, CERM, 0.1 uF, 250 V,+/- 20%, X7T, 0805; Manufacturer: TDK; TaMin_C: -55°C; Polarized: N; SizeAreaWB_mm2: 6.75; Value1: Unknown; U/M: EA; Value: 0.1uF; TaMax_C: 125°C; SizeZ_mm: 1.45; SizeX_mm: 2; SizeY_mm: 1.25; Cap_Case: 0805; SizeArea_mm2: 2.5; Cap_F: 100nF; AEC Category: Q200
C5 C6 = CMP-0009054-2: CAP, CERM, 470 pF, 500 V, +/- 10%, X7R, 1206; Manufacturer: Vishay-Vitramon; TaMin_C: -55°C; Polarized: N; SizeAreaWB_mm2: 10.92; Value1: Unknown; U/M: EA; Value: 470pF; TaMax_C: 125°C; SizeZ_mm: 1.35; SizeX_mm: 3.2; SizeY_mm: 1.6; SizeArea_mm2: 5.12; AEC Category: Q200
C8 C74 C147 = CMP-0078625-1: CAP, CERM, 1 µF, 25 V,+/- 20%, X5R, 0402; Manufacturer: MuRata; SizeAreaWB_mm2: 3; SizeArea_mm2: 0.5; AEC Qualified: N; AEC Category: Q200; Value: 1uF; TaMax_C: 85°C; SizeZ_mm: 0.6; TaMin_C: -55°C; U/M: EA; SizeX_mm: 1
C10-C13 = CMP-0105033-1: WCAP-CSGP Multilayer Ceramic Chip Capacitor, General Purpose, size 1210, X7R, 2.2µF, 100VDC; Manufacturer: Wurth Elektronik; Capacitance Tolerance: +/-10%; Case/Size Code: 1210; Dissipation Factor: 5%; Insulation Resistance: 0.05GOhm; Rated Voltage (DC): 100V; Technical Reference: X7R1210225K100DFCT10000
C14-C19 C141-C145 = CMP-0007891-2: CAP, CERM, 1 uF, 100 V, +/- 10%, X7S, 0805; Manufacturer: TDK; TaMin_C: -55°C; ESR_ohm: 8.255m; Polarized: N; SizeAreaWB_mm2: 6.75; Value1: 0.008255 ohm; U/M: EA; Value: 1uF; TaMax_C: 125°C; SizeZ_mm: 1.45; SizeX_mm: 2; SizeY_mm: 1.25; Cap_Case: 0805; SizeArea_mm2: 2.5; Cap_F: 1µF; IRMS_A: 2.27442A; AEC Category: Q200
C23-C28 C37-C43 C45 C47 C48 C57-C60 = CMP-0009135-2: CAP, CERM, 4.7 uF, 100 V, +/- 10%, X7S, 1210; Manufacturer: TDK; TaMin_C: -55°C; Polarized: N; SizeAreaWB_mm2: 14.7; Value1: Unknown; U/M: EA; Value: 4.7uF; TaMax_C: 125°C; SizeZ_mm: 1.35; SizeX_mm: 3.2; SizeY_mm: 2.5; SizeArea_mm2: 8; Cap_F: 4.7µF; AEC Category: Q200
C30 C31 = CMP-0009030-2: CAP, CERM, 100 pF, 1000 V, +/- 5%, C0G/NP0, 1206; Manufacturer: Vishay-Vitramon; TaMin_C: -55°C; Polarized: N; SizeAreaWB_mm2: 10.92; Value1: Unknown; U/M: EA; Value: 100pF; TaMax_C: 125°C; SizeZ_mm: 1.35; SizeX_mm: 3.2; SizeY_mm: 1.6; Value2: 1000V; SizeArea_mm2: 5.12; AEC Category: Q200
C33-C36 = CMP-0009843-2: CAP, AL, 470 uF, 100 V, +/- 20%, TH; Manufacturer: Panasonic; TaMin_C: -40°C; Polarized: Y; SizeAreaWB_mm2: 324; Value1: Unknown; U/M: EA; Value: 470uF; TaMax_C: 85°C; SizeZ_mm: 27; SizeX_mm: 16; Cap_Case: 16x25mm; SizeArea_mm2: 256; CompType: Capacitor; AEC Qualified: N; Cap_F: 470µF; IRMS_A: 9dA; AEC Category: Q200
C49-C52 = CMP-0110669-1: WCAP-ASLI Aluminum Electrolytic Capacitor, V-Chip, D16 x H17mm, 150uF, 100V; Manufacturer: Wurth Elektronik; Cap_F: 150µF; Capacitance Tolerance: +/-20%; Dissipation Factor: 10%; Endurance: 2000h; Leakage Current: 150uA; Ripple Current: 500mA; Technical Reference: ASEK170151M100DVCTHB000
C55 C56 = CMP-0081010-1: CAP, CERM, 2.2 µF, 25 V,+/- 20%, X5R, 0402; Manufacturer: MuRata; SizeAreaWB_mm2: 3; SizeArea_mm2: 0.5; AEC Qualified: N; AEC Category: Q200; Value: 2.2uF; TaMax_C: 85°C; SizeZ_mm: 0.6; TaMin_C: -55°C; U/M: EA; SizeX_mm: 1
C61 C62 = CMP-0009275-2: CAP, CERM, 0.1 uF, 100 V, +/- 10%, X7R, 1210; Manufacturer: Vishay-Vitramon; TaMin_C: -55°C; Polarized: N; SizeAreaWB_mm2: 14.7; Value1: Unknown; U/M: EA; Value: 0.1uF; TaMax_C: 125°C; SizeZ_mm: 1.35; SizeX_mm: 3.2; SizeY_mm: 2.5; SizeArea_mm2: 8; Cap_F: 100nF; AEC Category: Q200
C64-C73 = CMP-0097294-1: 0.1 µF ±10% 100V Ceramic Capacitor X7R 0603 (1608 Metric); Manufacturer: Wurth Electronics; TempCo: 15%; SizeZ_mm: 0.87mm; Value: 100nF; AEC Qualified: No
C77 C78 = CMP-0053309-1: WCAP-CSGP Multilayer Ceramic Chip Capacitor, General Purpose, size 0402, X7R, 100pF, 50VDC; Manufacturer: Wurth Elektronik; Capacitance Tolerance: +/-10%; Case/Size Code: 0402; Dissipation Factor: 2.5%; Insulation Resistance: 10GOhm; Technical Reference: X7R0402101K050DFCT10000; Rated Voltage (DC): 50V
C79-C81 C86 C87 C91 C97 C98 = CMP-0104156-1: WCAP-CSGP Multilayer Ceramic Chip Capacitor, General Purpose, size 0402, NP0, 33pF, 50VDC; Manufacturer: Wurth Elektronik; Capacitance Tolerance: +/-5%; Case/Size Code: 0402; Insulation Resistance: 10GOhm; Q Factor: 1000; Rated Voltage (DC): 50V; Technical Reference: NP00402330J050DFCT10000
C82 C83 C93 C94 = CMP-0006213-2: CAP, CERM, 33 pF, 25 V, +/- 5%, C0G/NP0, 0402; Manufacturer: Wurth Elektronik; TaMin_C: -55°C; Polarized: N; SizeAreaWB_mm2: 3; Value1: Unknown; U/M: EA; Value: 33pF; TaMax_C: 125°C; SizeZ_mm: 0.6; SizeX_mm: 1; SizeY_mm: 0.5; AEC Category: Q200
C84 C85 C95 C96 = CMP-0052531-1: WCAP-CSGP Multilayer Ceramic Chip Capacitor, General Purpose, size 0402, X7R, 100nF, 16VDC; Manufacturer: Wurth Elektronik; Capacitance Tolerance: +/-10%; Case/Size Code: 0402; Dissipation Factor: 5%; Insulation Resistance: 5GOhm; Rated Voltage (DC): 16V; Technical Reference: X7R0402104K016DFCT10000
C88 = CMP-0119248-1: WCAP-CSGP Multilayer Ceramic Chip Capacitor, General Purpose, size 0402, X7R, 100nF, 10VDC; Manufacturer: Wurth Elektronik; Capacitance Tolerance: +/-10%; Case/Size Code: 0402; Dissipation Factor: 5%; Insulation Resistance: 5GOhm; Rated Voltage (DC): 10V; Technical Reference: X7R0402104K010DFCT10000
C89 = CMP-0107736-1: WCAP-CSGP Multilayer Ceramic Chip Capacitor, General Purpose, size 0402, NP0, 1nF, 50VDC; Manufacturer: Wurth Elektronik; Capacitance Tolerance: +/-5%; Case/Size Code: 0402; Insulation Resistance: 10GOhm; Q Factor: 1000; Rated Voltage (DC): 50V; Technical Reference: NP00402102J050DFCT10000
C90 = CMP-0119280-1: WCAP-CSGP Multilayer Ceramic Chip Capacitor, General Purpose, size 0402, X7R, 10nF, 25VDC; Manufacturer: Wurth Elektronik; Capacitance Tolerance: +/-10%; Case/Size Code: 0402; Dissipation Factor: 3.5%; Insulation Resistance: 10GOhm; Rated Voltage (DC): 25V; Technical Reference: X7R0402103K025DFCT10000
C92 = CMP-0116016-1: WCAP-CSRF Multilayer Ceramic Chip Capacitor, High Frequency, size 0402, NP0 Class I, 22pF, 50VDC; Manufacturer: Wurth Elektronik; Capacitance Tolerance: +/-5%; Case/Size Code: 0402; Insulation Resistance: 10GOhm; Q Factor: 840; Rated Voltage (DC): 50V; Technical Reference: NP00402220J050DFCT1R000
C123 C124 = CMP-0119652-1: WCAP-CSGP Multilayer Ceramic Chip Capacitor, General Purpose, size 1206, X7R, 100nF, 100VDC; Manufacturer: Wurth Elektronik; Capacitance Tolerance: +/-10%; Case/Size Code: 1206; Dissipation Factor: 2.5%; Insulation Resistance: 1GOhm; Rated Voltage (DC): 100V; Technical Reference: X7R1206104K100DFCT10000
C125 = CMP-0009043-2: CAP, CERM, 0.01 uF, 1000 V, +/- 10%, X7R, 1206; Manufacturer: Vishay-Vitramon; TaMin_C: -55°C; Polarized: N; SizeAreaWB_mm2: 10.92; Value1: Unknown; U/M: EA; Value: 0.01uF; TaMax_C: 125°C; SizeZ_mm: 1.35; SizeX_mm: 3.2; SizeY_mm: 1.6; Value2: 1000V; SizeArea_mm2: 5.12; Cap_F: 10nF; AEC Category: Q200
C146 = CMP-0006253-2: CAP, CERM, 1 uF, 35 V, +/- 10%, JB, 0402; Manufacturer: TDK; TaMin_C: -25°C; Polarized: N; SizeAreaWB_mm2: 3; Value1: Unknown; U/M: EA; Value: 1uF; TaMax_C: 85°C; SizeZ_mm: 0.6; SizeX_mm: 1; SizeY_mm: 0.5; Cap_Case: 0402; Cap_F: 1µF; AEC Category: Q200
C153 = CMP-0114900-1: WCAP-CSGP Multilayer Ceramic Chip Capacitor, General Purpose, size 0402, NP0, 47pF, 50VDC; Manufacturer: Wurth Elektronik; Capacitance Tolerance: +/-5%; Case/Size Code: 0402; Insulation Resistance: 10GOhm; Q Factor: 1000; Rated Voltage (DC): 50V; Technical Reference: NP00402470J050DFCT10000
D1 D2 = CMP-0122261-1: Diode 200 V 2A Surface Mount SOD-123W; Manufacturer: Nexperia; AEC Qualified: No; SizeZ_mm: 1.1mm; TJmax_C: 175°C; Vf_V: 200V; Cap_F: 17pF; Max Surge Forward Current: 50A; Peak Reverse Current: 0.01uA; TaMax_C: +175°C; TaMin_C: -55°C
D3-D6 = CMP-0122254-1: Diode Schottky 40V 0.25A 2-Pin SOD-523 T/R; Manufacturer: Diodes Inc.; AEC Qualified: Yes; SizeZ_mm: 0.65mm; TJmax_C: 125°C; AEC Grade: Grade 1; Cap_F: 50pF; Forward Current: 250mA; Max Surge Forward Current: 1A; Peak Reverse Current: 5uA
L1 = CMP-0124159-1: 1 µH Shielded Molded Inductor 48.2 A 1.61mOhm Max Nonstandard; Manufacturer: Wurth; AEC Grade: Grade 1; AEC Qualified: Yes; DCR_ohm: 1.61m; Ind_H: 1µH; Irms: 48.2A; Isat: 25A; Material: Composite; SizeZ_mm: 9.1mm; Value: 1uH; Self Resonant Frequency: 40MHz; Shrouded: true; Standoff Height: 0.6mm; TaMax_C: +85°C; TaMin_C: -40°C; Test Frequency: 100kHz; Tolerance_%: 20%
L2 = CMP-0099219-1: WE-XHMI SMT Power Inductor, size 1510, 6.8uH, 15A, 4.1mOhm; Manufacturer: Wurth Elektronik; Case/Size Code: 1510; Performance Rated Current: 25.3A; Saturation Current: 40.05A; Self Resonant Frequency: 14MHz
Q5 = CMP-0092601-1: N-Channel 150 V 114A (Tc) 214W (Tc) Surface Mount, Wettable Flank PG-TSON-8-3; Manufacturer: Infineon; Threshold Vgs Min: 3V; Pulse Drain Current: 456A; Drain To Source Breakdown Voltage: 150V; AEC Qualified: No; Input Capacitace At Vds: 3100pF @ 75V; VdsMax_V: 1.2V; Rdson45_ohm: 6m; Turn On Delay Time: 9ns; Vgs_V: 20V; Reverse Recovery Charge: 23nC; Threshold Vgs Max: 4.6V; Transconductance: 81S; Turn Off Delay Time: 15ns; Number Of Channels: 1; Typ Forward Diode Voltage: 0.85V; Rthja Max: 50°C/W; SizeZ_mm: 1.1mm; Reverse Recovery Time: 29ns; ChMode: False; QgTyp_nC: 41nC @ 10V; TJmax_C: +175°C
R1-R6 = CMP-0018106-2: RES, 24.9, 1%, 0.25 W, 1206; Manufacturer: Yageo America; Power_W: 250mW; TempCo: 100 ppm/C; Value_Code: 24R9; U/M: EA; Value: 24.9; EIA_Code: E96; SizeX_mm: 3.2; SizeY_mm: 1.6; SizeZ_mm: 1.35; Value2: 0.25W; SizeArea_mm2: 5.12; VDC_V: 200V; AEC Category: Q200
R7 R8 R10 = CMP-0015972-3: RES, 4.7 k, 5%, 1 W, AEC-Q200 Grade 0, 2512; Manufacturer: Vishay-Dale; Power_W: 1W; TempCo: 200 ppm/C; Value_Code: 4k70; Value: 4.7k; EIA_Code: E24; SizeX_mm: 6.3; SizeY_mm: 3.2; SizeZ_mm: 0.71; SizeArea_mm2: 20.16; AEC Qualified: Y; VDC_V: 500V; AEC Grade: 0; AEC Category: Q200
R9 R11 R14 R16-R19 R25 R28 R34-R38 = CMP-0027004-2: RES, 0, 5%, 0.063 W, 0402; Manufacturer: Yageo America; Power_W: 63mW; TempCo: 200 ppm/C; Value_Code: 0000; U/M: EA; Value: 0; EIA_Code: E24; SizeX_mm: 1; SizeY_mm: 0.5; SizeZ_mm: 0.6; Value2: 0.063W; VDC_V: 50V; AEC Category: Q200
R12 R13 R26 R27 = CMP-0026926-3: RES, 3.3, 5%, 0.063 W, AEC-Q200 Grade 0, 0402; Manufacturer: Vishay-Dale; Power_W: 63mW; TempCo: 200 ppm/C; Value_Code: 3R30; Value: 3.3; EIA_Code: E24; SizeX_mm: 1; SizeY_mm: 0.5; SizeZ_mm: 0.6; Value2: 0.063W; AEC Qualified: Y; VDC_V: 50V; AEC Category: Q200; AEC Grade: 0
R15 R33 R58 R60 R111 R134 = CMP-0026658-1: RES, 10.0 k, 1%, 0.1 W, 0402; Manufacturer: Panasonic; Power_W: 100mW; TempCo: 100 ppm/C; Value_Code: 10k0; U/M: EA; Value: 10.0k; EIA_Code: E96; Res_ohm: 10k; SizeX_mm: 1; SizeY_mm: 0.5; SizeZ_mm: 0.6; Value2: 0.1W; VDC_V: 50V; AEC Category: Q200
R20 R39 = CMP-0026700-1: RES, 4.70 k, 1%, 0.1 W, 0402; Manufacturer: Panasonic; Power_W: 100mW; TempCo: 100 ppm/C; Value_Code: 4k70; U/M: EA; Value: 4.70k; Res_ohm: 4.7k; SizeX_mm: 1; SizeY_mm: 0.5; SizeZ_mm: 0.6; Value2: 0.1W; VDC_V: 50V; AEC Category: Q200
R21-R24 = CMP-0018312-2: RES, 46.4, 1%, 0.25 W, 1206; Manufacturer: Yageo America; Power_W: 250mW; TempCo: 100 ppm/C; Value_Code: 46R4; U/M: EA; Value: 46.4; EIA_Code: E96; SizeX_mm: 3.2; SizeY_mm: 1.6; SizeZ_mm: 1.35; Value2: 0.25W; SizeArea_mm2: 5.12; VDC_V: 200V; AEC Category: Q200
R29 R30 R40 R41 R44 R45 R62 R63 R65 R66 = CMP-0026749-1: RES, 10.0, 1%, 0.063 W, 0402; Manufacturer: KOA Speer; Power_W: 63mW; TempCo: 100 ppm/C; Value_Code: 10R0; U/M: EA; Value: 10.0; EIA_Code: E96; Res_ohm: 10; SizeX_mm: 1; SizeY_mm: 0.5; SizeZ_mm: 0.6; Value2: 0.063W; AEC Qualified: N; VDC_V: 50V; AEC Category: Q200
R31 R32 = CMP-0026194-2: RES, 249, 1%, 0.063 W, AEC-Q200 Grade 0, 0402; Manufacturer: Vishay-Dale; Power_W: 63mW; TempCo: 100 ppm/C; Value_Code: 249R; Value: 249; EIA_Code: E96; SizeX_mm: 1; SizeY_mm: 0.5; SizeZ_mm: 0.6; Value2: 0.063W; AEC Qualified: Y; VDC_V: 50V; AEC Category: Q200; AEC Grade: 0
R42 R43 R56 R61 R64 = CMP-0026763-1: RES, 100, 1%, 0.063 W, AEC-Q200 Grade 0, 0402; Manufacturer: Stackpole Electronics Inc; Power_W: 63mW; TempCo: 100 ppm/C; Value_Code: 100R; U/M: EA; Value: 100; EIA_Code: E96; SizeX_mm: 1; SizeY_mm: 0.5; SizeZ_mm: 0.6; Value2: 0.063W; AEC Qualified: Y; AEC Grade: 0; AEC Category: Q200
R46 R47 R57 R59 = CMP-0078583-1: RES, 15.0 k, 1%, 0.063 W, 0402; Manufacturer: Yageo America; Power_W: 63mW; Green_Lifecycle: Active; TempCo: 100 ppm/C; Value_Code: 15k0; Green_REACh: Passed; Value: 15.0k; EIA_Code: E96; Res_ohm: 15k; SizeX_mm: 1; SizeY_mm: 0.5; SizeZ_mm: 0.6; Value2: 0.063W; AEC Qualified: N; AEC Category: Q200
R48 = CMP-0026735-1: RES, 470 k, 1%, 0.0625 W, 0402; Manufacturer: Yageo America; Power_W: 62.5mW; TempCo: 100 ppm/C; U/M: EA; Value: 470k; SizeX_mm: 1; SizeY_mm: 0.5; SizeZ_mm: 0.6; AEC Qualified: N; VDC_V: 50V; AEC Category: Q200
R49 R51 R54 = CMP-0026717-1: RES, 10.0, 1%, 0.063 W, 0402; Manufacturer: Rohm; Power_W: 63mW; TempCo: 100 ppm/C; Value_Code: 10R0; U/M: EA; Value: 10.0; EIA_Code: E96; Res_ohm: 10; SizeX_mm: 1; SizeY_mm: 0.5; SizeZ_mm: 0.6; Value2: 0.063W; AEC Qualified: N; VDC_V: 50V; AEC Category: Q200
R50 R52 R53 = CMP-0026657-1: RES, 1.00 k, 1%, 0.1 W, 0402; Manufacturer: Panasonic; Power_W: 100mW; TempCo: 100 ppm/C; Value_Code: 1k00; U/M: EA; Value: 1.00k; EIA_Code: E96; Res_ohm: 1k; SizeX_mm: 1; SizeY_mm: 0.5; SizeZ_mm: 0.6; Value2: 0.1W; VDC_V: 50V; AEC Category: Q200
R55 = CMP-0027004-2: RES, 0, 5%, 0.063 W, 0402; Manufacturer: Yageo America; PartNumber: RC0402JR-070RL; Power_W: 63mW; TempCo: 200 ppm/C; Value_Code: 0000; U/M: EA; Value: 0; EIA_Code: E24; SizeX_mm: 1; SizeY_mm: 0.5; SizeZ_mm: 0.6; Value2: 0.063W; VDC_V: 50V; AEC Category: Q200
R109 R110 = CMP-0026749-1: RES, 10.0, 1%, 0.063 W, 0402; Manufacturer: KOA Speer; PartNumber: RK73H1ETTP10R0F; Power_W: 63mW; TempCo: 100 ppm/C; Value_Code: 10R0; U/M: EA; Value: 10.0; EIA_Code: E96; Res_ohm: 10; SizeX_mm: 1; SizeY_mm: 0.5; SizeZ_mm: 0.6; Value2: 0.063W; AEC Qualified: N; VDC_V: 50V; AEC Category: Q200
R129 = CMP-0026481-2: RES, 5.62, 1%, 0.063 W, AEC-Q200 Grade 0, 0402; Manufacturer: Vishay-Dale; Power_W: 63mW; TempCo: 100 ppm/C; Value_Code: 5R62; Value: 5.62; EIA_Code: E96; SizeX_mm: 1; SizeY_mm: 0.5; SizeZ_mm: 0.6; Value2: 0.063W; AEC Qualified: Y; VDC_V: 50V; AEC Category: Q200; AEC Grade: 0
R132 = CMP-0026747-1: RES, 2.20, 1%, 0.2 W, 0402; Manufacturer: Vishay-Dale; Power_W: 200mW; TempCo: 100 ppm/C; Value_Code: 2R20; U/M: EA; Value: 2.20; Res_ohm: 2.2; SizeX_mm: 1; SizeY_mm: 0.5; SizeZ_mm: 0.6; Value2: 0.2W; AEC Qualified: N; AEC Category: Q200
RS1 = CMP-0018759-2: RES, 0, 5%, 0.25 W, 1206; Manufacturer: Yageo America; Power_W: 250mW; TempCo: 200 ppm/C; Value_Code: 0000; U/M: EA; Value: 0; EIA_Code: E24; SizeX_mm: 3.2; SizeY_mm: 1.6; SizeZ_mm: 1.35; Value2: 0.25W; SizeArea_mm2: 5.12; VDC_V: 200V; AEC Category: Q200
RSENSE1 = CMP-0089827-1: 1 mOhms ±1% 5W Chip Resistor 2512 (6432 Metric) Automotive AEC-Q200, Current Sense, Moisture Resistant, Pulse Withstanding Metal Element; Manufacturer: Vishay; SizeZ_mm: 0.81mm; AEC Grade: Grade 0; Standoff Height: 0.32mm; AEC Qualified: Yes; TempCo: 170ppm/°C; Res_ohm: 1m
T1 = CMP-0124000-1: Transformer; Manufacturer: Cyntec; DCR_ohm: 1.5m; Ind_H: 40µH; Ns1toNp: 3:5; Rsec1_ohm: 3.9m; SizeZ_mm: 9.37mm; AEC Qualified: No; Voltage_Isolation_Vrms: 1500VDC
U1 U4 = CMP-0120692-1: 100-V, 53-A GaN Half-Bridge Power Stage; Manufacturer: Texas Instruments; Part Number: LMG2100R026; SizeZ_mm: 0.85mm; AEC Qualified: No; Max Supply Voltage: 5.25V; Min Supply Voltage: 4.75V; Nominal Supply Current: 12mA; Number Of Outputs: 1; Standoff Height: 0mm; TJmax_C: +125°C
U2 U3 U5 U6 = CMP-0037654-1: 100-V, 64-A GaN with Integrated Driver; Manufacturer: Texas Instruments; SizeZ_mm: 0.85mm; AEC Qualified: No; Max Supply Voltage: 5.25V; Min Supply Voltage: 4.75V; Nominal Supply Current: 3mA; Number Of Drivers: 1; Propagation Delay: 55ns; Standoff Height: 0mm; TJmax_C: +125°C
U7 U9 = CMP-0095064-1: CAN, RS232, RS485, SPI Digital Isolator 3000Vrms 2 Channel 50Mbps 50kV/µs CMTI 8-SOIC (0.154", 3.90mm Width); Manufacturer: Texas Instruments; Part Number: ISO6720BDR; AEC Qualified: No; TaMax_C: +125°C; Standoff Height: 0.11mm; TaMin_C: -40°C; Max Supply Voltage: 5.5V; TJmax_C: +150°C; SizeZ_mm: 1.75mm; Min Supply Voltage: 1.71V
U8 = CMP-0032028-2: CMOS Amplifier 1 Circuit Rail-to-Rail SOT-23-5; Manufacturer: Texas Instruments; SizeZ_mm: 1.45mm; AEC Qualified: No; Gain Bandwidth: 50MHz; Input Bias Current: 0.000005uA; Input Offset Voltage: 0.4mV; Max Supply Voltage: 5.5V; Min Supply Voltage: 2.2V; Nominal Supply Current: 4.6mA; Number Of Channels: 1; Output Current Per Channel: 85mA; Response Time: 0.2us; Standoff Height: 0mm; TaMax_C: +125°C; TaMin_C: -40°C; TJmax_C: +150°C; Voltage Gain: 120dB; AEC Category: Q200; CompType: IC
U15 = CMP-0122620-1: 3kVrms, 5A/5A single-channel isolated gate driver with miller clamp or split out & 8V or 12V UVLO; Manufacturer: Texas Instruments; SizeZ_mm: 1.75mm; AEC Qualified: No; Fall Time: 10ns; Max Power Dissipation: 1.14W; Max Supply Voltage: 33V; Min Supply Voltage: 3V; Number Of Drivers: 2; Propagation Delay: 65ns; Standoff Height: 0.11mm; TaMax_C: +125°C; TaMin_C: -40°C; TJmax_C: +150°C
